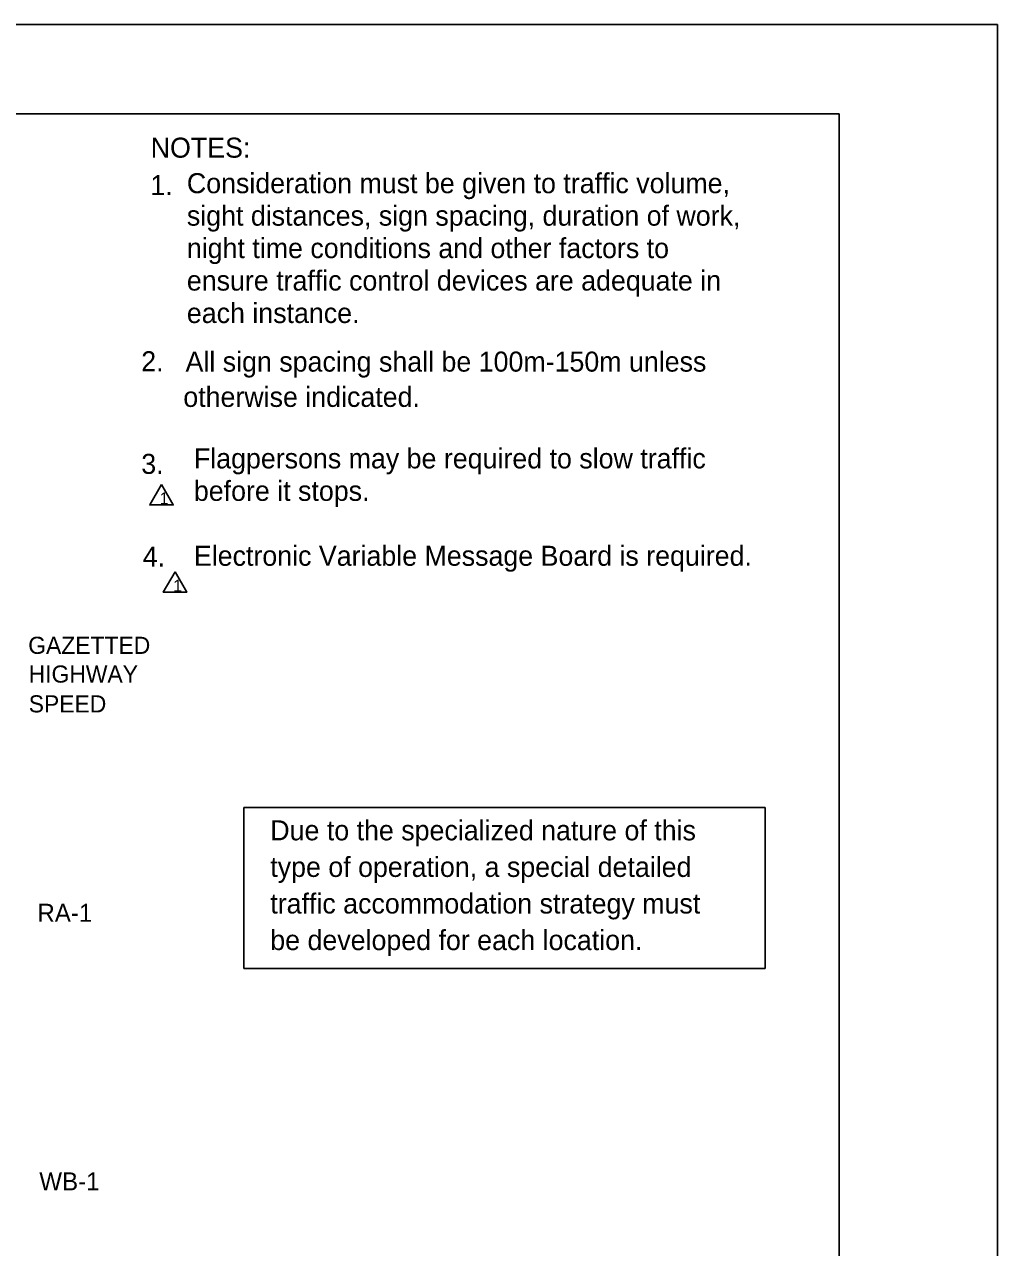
# Model space of a CAD drawing. Extents: x 1314 to 1530, y 165 to 444.
# Drawn here: x 1412.2 to 1529.8, y 296.1 to 443.9 of the extents above; entities that cross this region are included whole.
import ezdxf

# ---------------------------------------------------------------- set-up
doc = ezdxf.new("R2010")
doc.units = 0
for name, color, linetype in [('Level 1', 7, 'Continuous'), ('Level 10', 7, 'Continuous'), ('Level 60', 7, 'Continuous')]:
    doc.layers.add(name, color=color, linetype=linetype)

msp = doc.modelspace()

# ---------------------------------------------------------------- linework, layer by layer
at = {"layer": 'Level 1'}
for points in [[(1428.8, 388.31), (1427.38, 385.84), (1430.22, 385.84)], [(1430.43, 377.76), (1429.01, 375.29), (1431.85, 375.29)]]:
    msp.add_lwpolyline(points, close=True, dxfattribs=at)
at = {"layer": 'Level 10'}
msp.add_lwpolyline([(1438.76, 349.28), (1501.73, 349.28), (1501.73, 329.85), (1438.76, 329.85)], close=True, dxfattribs=at)
at = {"layer": 'Level 60'}
msp.add_line((1529.82, 443.87), (1529.82, 443.87), dxfattribs=at)
for points in [[(1529.82, 443.87), (1313.82, 443.87), (1313.82, 164.87), (1529.82, 164.87)], [(1510.69, 433.06), (1323.82, 433.06), (1323.82, 175.68), (1510.69, 175.68)]]:
    msp.add_lwpolyline(points, close=True, dxfattribs=at)

# ---------------------------------------------------------------- texts
at = {"layer": 'Level 1'}
for p in [(1428.57, 385.9), (1430.2, 375.35)]:
    msp.add_text('1', height=1.45, rotation=360, dxfattribs=at).set_placement(p)
at = {"layer": 'Level 10'}
for s, p in [('NOTES:', (1427.49, 427.78)), ('1.', (1427.44, 423.26)), ('Consideration must be given to traffic volume,', (1431.86, 423.49)), ('sight distances, sign spacing, duration of work,', (1431.86, 419.57)), ('night time conditions and other factors to', (1431.86, 415.65)), ('ensure traffic control devices are adequate in', (1431.86, 411.73)), ('each instance.', (1431.86, 407.81)), ('2.', (1426.35, 401.98)), ('All sign spacing shall be 100m-150m unless', (1431.7, 401.94)), ('otherwise indicated.', (1431.43, 397.68)), ('3.', (1426.35, 389.59)), ('Flagpersons may be required to slow traffic ', (1432.71, 390.25)), ('before it stops.', (1432.71, 386.33)), ('4.', (1426.53, 378.4)), ('Electronic Variable Message Board is required.', (1432.71, 378.49)), ('Due to the specialized nature of this ', (1441.94, 345.33)), ('type of operation, a special detailed ', (1441.94, 340.91)), ('traffic accommodation strategy must ', (1441.94, 336.49)), ('be developed for each location.', (1441.94, 332.07))]:
    msp.add_text(s, height=2.419, dxfattribs=at).set_placement(p)
for s, height, p in [('GAZETTED', 2.068, (1412.69, 367.85)), ('HIGHWAY', 2.068, (1412.74, 364.38)), ('SPEED', 2.068, (1412.75, 360.78)), ('RA-1', 2.177, (1413.8, 335.49)), ('WB-1', 2.177, (1414.03, 303.05))]:
    msp.add_text(s, height=height, rotation=360, dxfattribs=at).set_placement(p)

doc.saveas('drawing.dxf')
